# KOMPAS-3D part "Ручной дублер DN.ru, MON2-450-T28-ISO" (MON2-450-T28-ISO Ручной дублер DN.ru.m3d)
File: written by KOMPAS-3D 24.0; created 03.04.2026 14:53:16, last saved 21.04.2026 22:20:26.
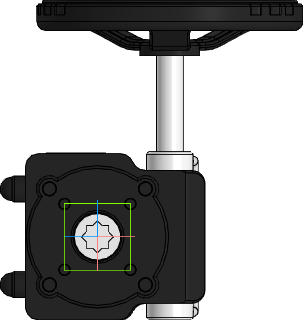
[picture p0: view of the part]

Document properties: Автор: R2D2; Полное имя файла: MON2-450-T28-ISO Ручной дублер DN.ru.cdw

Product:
- Body: Тело 4  | qty 1
    Масса: 12.336453
- Part/product: Ручной дублер DN.ru  | designation MON2-450-T28-ISO
    Масса: 4.5
    Раздел спецификации: Прочие изделия
    Форматы листов документа: A2
    Примечание: D290-00337

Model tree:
1. Операция без истории:1

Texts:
  MON2-450-T28-ISO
